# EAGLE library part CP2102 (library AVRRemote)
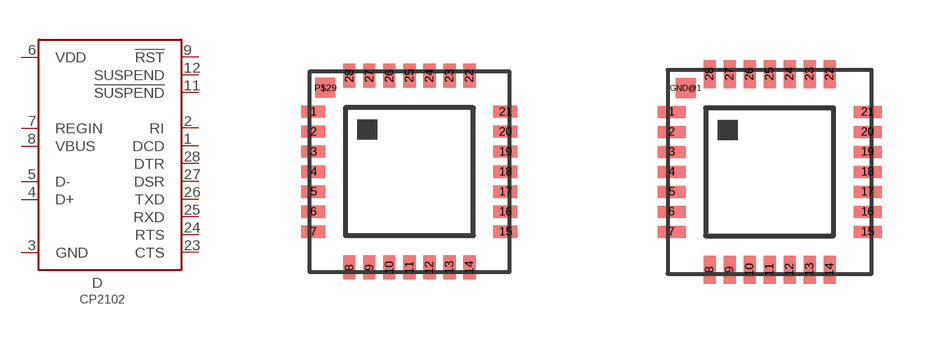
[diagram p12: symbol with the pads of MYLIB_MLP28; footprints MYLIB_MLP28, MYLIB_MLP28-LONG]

Designator prefix D

## CP2102  [MYLIB_MLP28]
1  DCD
2  RI
3  GND
4  D+
5  D-
6  VDD
7  REGIN
8  VBUS
9  !RST
11  !SUSPEND
12  SUSPEND
23  CTS
24  RTS
25  RXD
26  TXD
27  DSR
28  DTR

## CP2102LONG  [MYLIB_MLP28-LONG]
Pads as for MYLIB_MLP28

## Footprint MYLIB_MLP28 (pad centres in mm)
smd 0.6 x 0.3: 1 -2.4,1.5; 2 -2.4,1; 3 -2.4,0.5; 4 -2.4,0; 5 -2.4,-0.5; 6 -2.4,-1; 7 -2.4,-1.5; 15 2.4,-1.5; 16 2.4,-1; 17 2.4,-0.5; 18 2.4,0; 19 2.4,0.5; 20 2.4,1; 21 2.4,1.5
smd 0.3 x 0.6: 8 -1.5,-2.4; 9 -1,-2.4; 10 -0.5,-2.4; 11 0,-2.4; 12 0.5,-2.4; 13 1,-2.4; 14 1.5,-2.4; 22 1.5,2.4; 23 1,2.4; 24 0.5,2.4; 25 0,2.4; 26 -0.5,2.4; 27 -1,2.4; 28 -1.5,2.4
smd 0.5 x 0.5: P$29 -2.1,2.1

## Footprint MYLIB_MLP28-LONG (pad centres in mm)
smd 0.7 x 0.3: 1 -2.45,1.5; 2 -2.45,1; 3 -2.45,0.5; 4 -2.45,0; 5 -2.45,-0.5; 6 -2.45,-1; 7 -2.45,-1.5; 15 2.45,-1.5; 16 2.45,-1; 17 2.45,-0.5; 18 2.45,0; 19 2.45,0.5; 20 2.45,1; 21 2.45,1.5
smd 0.3 x 0.7: 8 -1.5,-2.45; 9 -1,-2.45; 10 -0.5,-2.45; 11 0,-2.45; 12 0.5,-2.45; 13 1,-2.45; 14 1.5,-2.45; 22 1.5,2.45; 23 1,2.45; 24 0.5,2.45; 25 0,2.45; 26 -0.5,2.45; 27 -1,2.45; 28 -1.5,2.45
smd 0.5 x 0.5: GND@1 -2.1,2.1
